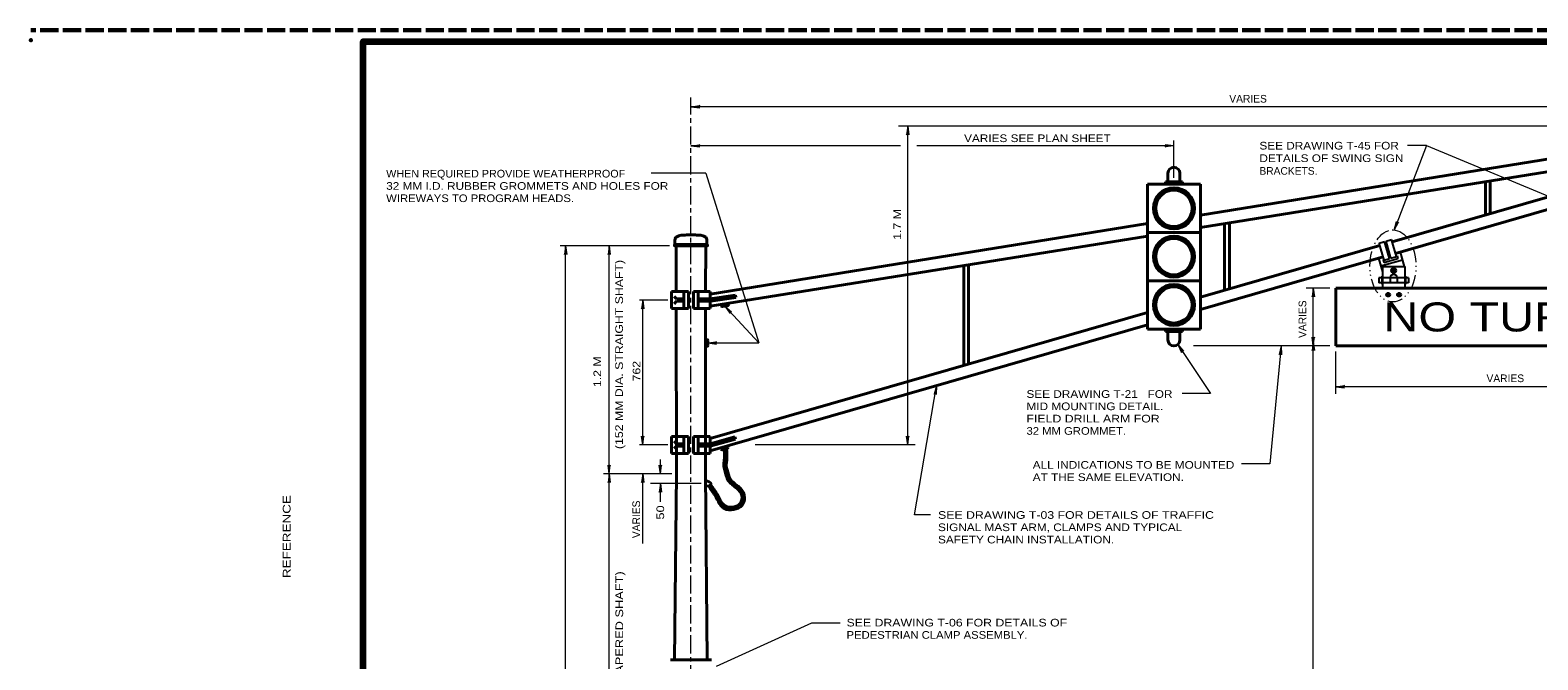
# Model space of a CAD drawing. Extents: x 312583 to 312853, y 144419 to 144586.
# Drawn here: x 312583.5 to 312733, y 144523.7 to 144586.2 of the extents above; entities that cross this region are included whole.
import ezdxf
from ezdxf.enums import TextEntityAlignment as Align

# ---------------------------------------------------------------- set-up
doc = ezdxf.new("R2010")
doc.units = 0
doc.header["$LTSCALE"] = 0.3
doc.header["$PDMODE"] = 32
doc.header["$PDSIZE"] = 0.15
for name, pattern in [('DASH_DOUBLE_DOT', [9.2, 5, -1.2, 0.3, -1.2, 0.3, -1.2]), ('LONG_DASH_SHORT_DASH', [9.9, 6, -1.2, 1.5, -1.2]), ('LONG_DASHED', [7.5, 6, -1.5])]:
    doc.linetypes.add(name, pattern=pattern)
for name, color, linetype, lineweight in [('1', 7, 'Continuous', 40), ('2', 7, 'Continuous', 13), ('63', 7, 'LONG_DASHED', 60)]:
    doc.layers.add(name, color=color, linetype=linetype, lineweight=lineweight)

msp = doc.modelspace()

# ---------------------------------------------------------------- hatches: boundary and pattern name
at = {"layer": '1'}
for points in [[(312718.9644, 144562.3791, 1), (312718.4824, 144562.3791, 1)], [(312718.8931, 144562.3791, 1), (312718.5537, 144562.3791, 1)], [(312718.3737, 144559.9738, 1), (312717.9914, 144559.9738, 1)], [(312719.4525, 144559.9738, 1), (312719.0702, 144559.9738, 1)]]:
    msp.add_hatch(color=256, dxfattribs=at).paths.add_polyline_path(points)

# ---------------------------------------------------------------- linework, layer by layer
for p, q in [((312699.5568, 144567.8759), (312754.2354, 144576.6849)), ((312699.5568, 144566.6493), (312754.4884, 144575.4813)), ((312696.0838, 144571.1803), (312697.7628, 144571.1803)), ((312696.0838, 144570.9426), (312696.0838, 144571.1803)), ((312696.3214, 144571.1803), (312696.3214, 144572.0236)), ((312697.5251, 144571.1803), (312697.5251, 144572.0236)), ((312697.7628, 144570.9426), (312697.7628, 144571.1803)), ((312718.5807, 144565.2268), (312740.3144, 144571.4967)), ((312727.8314, 144571.1956), (312727.8314, 144567.8989)), ((312728.3068, 144571.2723), (312728.3068, 144568.0369)), ((312694.2898, 144570.9426), (312699.5568, 144570.9426)), ((312694.2898, 144556.5676), (312694.2898, 144570.9426)), ((312699.5568, 144570.9426), (312699.5568, 144556.5676)), ((312718.9106, 144564.0723), (312740.6426, 144570.3417)), ((312650.9271, 144560.0406), (312694.2898, 144567.0249)), ((312701.9564, 144567.0326), (312701.9564, 144560.4316)), ((312702.4318, 144567.1093), (312702.4318, 144560.5696)), ((312647.4234, 144564.9549), (312647.4234, 144565.3153)), ((312650.5974, 144564.9549), (312650.5974, 144565.3153)), ((312650.9271, 144558.8293), (312694.2898, 144565.7983)), ((312694.2898, 144566.1509), (312699.5568, 144566.1509)), ((312650.5974, 144564.9549), (312647.3621, 144564.9549)), ((312647.5384, 144564.8323), (312649.0104, 144564.8323)), ((312647.5384, 144564.8323), (312647.5461, 144560.2783)), ((312650.4748, 144564.8323), (312649.0104, 144564.8323)), ((312650.4748, 144564.8323), (312650.4671, 144560.2783)), ((312650.5974, 144564.9549), (312650.6511, 144564.9549)), ((312699.5568, 144559.7416), (312717.3507, 144564.8725)), ((312699.5568, 144558.4919), (312717.6847, 144563.7192)), ((312717.8863, 144565.027), (312718.0344, 144565.0697)), ((312718.222, 144563.8741), (312718.3642, 144563.9151)), ((312676.0814, 144562.8696), (312676.0814, 144552.9719)), ((312676.5568, 144562.9463), (312676.5568, 144553.1099)), ((312694.2898, 144561.3593), (312699.5568, 144561.3593)), ((312747.5424, 144560.6386), (312712.9734, 144560.6386)), ((312712.9734, 144560.6386), (312712.9734, 144554.8886)), ((312647.0938, 144558.6069), (312647.0938, 144560.2783)), ((312648.7651, 144560.2783), (312647.0938, 144560.2783)), ((312647.3314, 144559.8029), (312647.5691, 144559.5653)), ((312647.3314, 144559.0823), (312647.5691, 144559.3199)), ((312648.2898, 144559.5653), (312647.5691, 144559.5653)), ((312648.2898, 144559.3199), (312647.5691, 144559.3199)), ((312648.2898, 144558.6069), (312648.2898, 144560.2783)), ((312648.7651, 144558.6069), (312648.7651, 144560.2783)), ((312649.2481, 144560.2783), (312650.9271, 144560.2783)), ((312649.2481, 144558.6069), (312649.2481, 144560.2783)), ((312649.7234, 144558.6069), (312649.7234, 144560.2783)), ((312650.9271, 144559.5653), (312649.7234, 144559.5653)), ((312650.9271, 144559.3199), (312649.7234, 144559.3199)), ((312650.9271, 144558.6069), (312650.9271, 144560.2783)), ((312650.9271, 144559.5653), (312653.4188, 144559.9409)), ((312650.9424, 144559.3199), (312653.4571, 144559.7109)), ((312653.4188, 144559.9409), (312653.4571, 144559.7109)), ((312648.7651, 144558.6069), (312647.0938, 144558.6069)), ((312647.5461, 144558.6069), (312647.5691, 144542.1926)), ((312649.2481, 144558.6069), (312650.9271, 144558.6069)), ((312650.4671, 144558.6069), (312650.4441, 144542.1926)), ((312650.9271, 144545.7116), (312694.2898, 144558.2236)), ((312652.0081, 144558.8829), (312651.9928, 144559.0056)), ((312652.1384, 144558.7986), (312652.6138, 144558.8676)), ((312652.7134, 144558.9903), (312652.6981, 144559.1129)), ((312650.9271, 144544.4696), (312694.2898, 144556.9739)), ((312694.2898, 144556.5676), (312699.5568, 144556.5676)), ((312696.0838, 144556.5676), (312696.0838, 144556.3299)), ((312696.0838, 144556.3299), (312697.7628, 144556.3299)), ((312696.3214, 144556.3299), (312696.3214, 144555.4866)), ((312697.5251, 144556.3299), (312697.5251, 144555.4866)), ((312697.7628, 144556.5676), (312697.7628, 144556.3299)), ((312650.5898, 144555.5479), (312650.4594, 144555.5479)), ((312650.5898, 144554.8349), (312650.4594, 144554.8349)), ((312650.6894, 144554.9499), (312650.6894, 144555.4329)), ((312747.5424, 144554.8886), (312712.9734, 144554.8886)), ((312647.0938, 144544.2319), (312647.0938, 144545.9033)), ((312648.7651, 144545.9033), (312647.0938, 144545.9033)), ((312648.2898, 144544.2319), (312648.2898, 144545.9033)), ((312648.7651, 144544.2319), (312648.7651, 144545.9033)), ((312649.2481, 144545.9033), (312650.9271, 144545.9033)), ((312649.2481, 144544.2319), (312649.2481, 144545.9033)), ((312649.7234, 144544.2319), (312649.7234, 144545.9033)), ((312650.9271, 144544.2319), (312650.9271, 144545.9033)), ((312650.9271, 144545.1903), (312653.3574, 144545.8573)), ((312653.3574, 144545.8573), (312653.4188, 144545.6273)), ((312648.7651, 144544.2319), (312647.0938, 144544.2319)), ((312647.3314, 144545.4279), (312647.5691, 144545.1903)), ((312647.3314, 144544.7073), (312647.5691, 144544.9449)), ((312648.2898, 144545.1903), (312647.5691, 144545.1903)), ((312648.2898, 144544.9449), (312647.5691, 144544.9449)), ((312649.2481, 144544.2319), (312650.9271, 144544.2319)), ((312650.9271, 144545.1903), (312649.7234, 144545.1903)), ((312650.9271, 144544.9449), (312649.7234, 144544.9449)), ((312650.9271, 144544.9373), (312653.4188, 144545.6273)), ((312652.0081, 144544.6613), (312651.9851, 144544.7609)), ((312652.1538, 144544.5923), (312652.6138, 144544.7149)), ((312652.6981, 144544.8453), (312652.6751, 144544.9526)), ((312647.5691, 144542.1926), (312647.3851, 144523.7466)), ((312650.4441, 144542.1926), (312650.6281, 144523.7466)), ((312651.0574, 144541.1806), (312650.6664, 144540.9429)), ((312651.0421, 144523.7466), (312646.9711, 144523.7466))]:
    msp.add_line(p, q, dxfattribs=at)
at = {"layer": '1', "lineweight": 25}
for p, q in [((312717.2873, 144565.0914), (312717.8244, 144565.2396)), ((312718.3152, 144563.5542), (312717.8244, 144565.2396)), ((312717.9726, 144565.2859), (312718.5189, 144565.4433)), ((312718.4541, 144563.6005), (312717.9726, 144565.2859)), ((312719.0004, 144563.7579), (312718.5189, 144565.4433)), ((312717.7781, 144563.3968), (312717.2873, 144565.0914)), ((312718.2874, 144563.6283), (312718.4448, 144563.6746)), ((312718.4541, 144563.6005), (312719.0004, 144563.7579)), ((312718.9819, 144563.8227), (312719.0653, 144563.8505)), ((312719.0653, 144563.8505), (312719.1486, 144563.5634)), ((312719.3616, 144564.2024), (312719.7681, 144562.7798)), ((312717.2317, 144563.5912), (312717.6214, 144562.2382)), ((312717.4547, 144562.8243), (312719.5846, 144563.4262)), ((312717.6214, 144562.7798), (312719.8254, 144562.7798)), ((312717.6214, 144562.7798), (312717.6214, 144560.6386)), ((312717.667, 144563.4523), (312717.7503, 144563.4708)), ((312717.667, 144563.4523), (312717.7503, 144563.156)), ((312717.7503, 144563.156), (312719.1486, 144563.5634)), ((312717.7781, 144563.3968), (312718.3152, 144563.5542)), ((312719.8254, 144562.7798), (312719.8254, 144560.6386)), ((312717.251, 144561.6484), (312717.251, 144561.1576)), ((312717.5473, 144561.6484), (312717.251, 144561.6484)), ((312717.5473, 144561.1576), (312717.251, 144561.1576)), ((312717.5473, 144561.8058), (312717.5473, 144561.0094)), ((312717.6214, 144561.8058), (312717.5473, 144561.8058)), ((312717.6214, 144561.0094), (312717.5473, 144561.0094)), ((312719.8254, 144561.6484), (312717.6214, 144561.6484)), ((312719.8254, 144561.1576), (312717.6214, 144561.1576)), ((312718.3715, 144561.6484), (312718.3715, 144561.1576)), ((312719.0753, 144561.6484), (312719.0753, 144561.1576)), ((312719.8994, 144561.8058), (312719.8254, 144561.8058)), ((312719.8994, 144561.0094), (312719.8254, 144561.0094)), ((312719.8994, 144561.8058), (312719.8994, 144561.0094)), ((312720.1958, 144561.6484), (312719.8994, 144561.6484)), ((312720.1958, 144561.1576), (312719.8994, 144561.1576)), ((312720.1958, 144561.6484), (312720.1958, 144561.1576))]:
    msp.add_line(p, q, dxfattribs=at)
at = {"layer": '1', "lineweight": 158}
msp.add_lwpolyline([(312616.5, 144423.1446), (312616.5, 144585.0846), (312849, 144585.0846)], dxfattribs=at)
at = {"layer": '1'}
for points in [[(312647.5384, 144564.8323), (312647.3621, 144564.8323), (312647.3621, 144564.9549)], [(312650.4748, 144564.8323), (312650.6511, 144564.8323), (312650.6511, 144564.9549)]]:
    msp.add_lwpolyline(points, dxfattribs=at)
for centre, radius in [((312696.9237, 144568.5458), 2.0365), ((312696.9237, 144568.5458), 1.7969), ((312696.9237, 144563.7541), 2.0365), ((312696.9237, 144563.7541), 1.7969), ((312696.9237, 144558.9625), 2.0365), ((312696.9237, 144558.9625), 1.7969)]:
    msp.add_circle(centre, radius, dxfattribs=at)
at = {"layer": '1', "lineweight": 25}
for centre, radius in [((312718.7234, 144562.3791), 0.241), ((312718.7234, 144562.3791), 0.1697), ((312718.1825, 144559.9738), 0.1911), ((312719.2613, 144559.9738), 0.1911)]:
    msp.add_circle(centre, radius, dxfattribs=at)
at = {"layer": '1'}
for centre, radius, start, end in [((312696.9237, 144572.0198), 0.599, 0, 180), ((312652.1231, 144558.9137), 0.1193, 195.83064, 278.98563), ((312652.5977, 144558.9866), 0.1193, 278.4852, 1.56735), ((312650.5731, 144554.9506), 0.1193, 277.08064, 0.23563), ((312650.5733, 144555.4308), 0.1193, 359.7352, 82.81735), ((312696.9237, 144555.4885), 0.599, 180, 0), ((312652.1198, 144544.7035), 0.1193, 202.50814, 285.66313), ((312652.5827, 144544.831), 0.1193, 285.1627, 8.24485), ((312650.5009, 144540.8365), 0.6575, 31.85561, 93.74313), ((312650.5009, 144540.8365), 0.1989, 31.87604, 102.98389)]:
    msp.add_arc(centre, radius, start, end, dxfattribs=at)
at = {"layer": '1', "lineweight": 25}
msp.add_arc((312718.7219, 144561.6237), 0.3533, 5.25702, 174.74298, dxfattribs=at)
at = {"layer": '1', "linetype": 'DASH_DOUBLE_DOT', "lineweight": 13}
msp.add_ellipse((312718.6496, 144562.8307), major_axis=(0, 3.5708), ratio=0.640077, dxfattribs=at)
at = {"layer": '1'}
for points in [[(312649.0104, 144565.9133), (312648.6654, 144565.9056), (312648.2284, 144565.8826), (312648.0214, 144565.8673), (312647.8144, 144565.8213), (312647.6688, 144565.7599), (312647.5384, 144565.6756), (312647.4464, 144565.5376), (312647.4311, 144565.4763), (312647.4234, 144565.3153)], [(312649.0104, 144565.9133), (312649.3478, 144565.9056), (312649.7848, 144565.8826), (312649.9918, 144565.8673), (312650.1988, 144565.8213), (312650.3444, 144565.7599), (312650.4748, 144565.6756), (312650.5668, 144565.5376), (312650.5821, 144565.4763), (312650.5974, 144565.3153)], [(312652.5371, 144544.6843), (312652.5524, 144543.5266), (312652.5064, 144543.0589), (312652.5984, 144542.5989), (312652.9204, 144541.6866), (312653.6871, 144540.9659), (312654.1011, 144540.5443), (312654.3158, 144539.6243), (312654.0781, 144539.0953), (312653.2501, 144538.6583), (312652.3378, 144538.7503), (312651.8471, 144539.2409), (312651.3948, 144540.0766), (312651.0651, 144540.5366), (312650.7584, 144540.9966)], [(312652.2994, 144544.6383), (312652.3148, 144543.5419), (312652.2688, 144543.0513), (312652.3684, 144542.5376), (312652.7134, 144541.5486), (312653.5184, 144540.7973), (312653.8864, 144540.4216), (312654.0628, 144539.6473), (312653.8941, 144539.2716), (312653.2041, 144538.9036), (312652.4528, 144538.9803), (312652.0388, 144539.3866), (312651.5941, 144540.1993), (312651.2644, 144540.6746), (312650.9578, 144541.1269)]]:
    msp.add_spline(points, degree=3, dxfattribs=at)
msp.add_point((312583.526, 144585.2246), dxfattribs=at)
at = {"layer": '2', "linetype": 'LONG_DASH_SHORT_DASH'}
msp.add_line((312649.0104, 144438.2556), (312649.0104, 144579.5523), dxfattribs=at)
at = {"layer": '2'}
for p, q in [((312649.0104, 144578.6323), (312649.8768, 144578.7396)), ((312763.5274, 144578.6323), (312649.0104, 144578.6323)), ((312649.0104, 144578.6323), (312649.8768, 144578.5249)), ((312649.8768, 144578.7396), (312649.6008, 144578.6323)), ((312649.8768, 144578.5249), (312649.6008, 144578.6323)), ((312751.6901, 144576.6926), (312669.5878, 144576.6926)), ((312670.5154, 144576.6926), (312670.4081, 144575.8263)), ((312670.4081, 144575.8263), (312670.5154, 144576.1023)), ((312670.5154, 144545.0676), (312670.5154, 144576.6926)), ((312670.5154, 144576.6926), (312670.6228, 144575.8263)), ((312670.6228, 144575.8263), (312670.5154, 144576.1023)), ((312649.0104, 144574.7529), (312649.8768, 144574.8603)), ((312669.8024, 144574.7529), (312649.0104, 144574.7529)), ((312649.0104, 144574.7529), (312649.8768, 144574.6456)), ((312649.8768, 144574.8603), (312649.6008, 144574.7529)), ((312649.8768, 144574.6456), (312649.6008, 144574.7529)), ((312696.9271, 144574.7529), (312671.4201, 144574.7529)), ((312696.0608, 144574.8603), (312696.3368, 144574.7529)), ((312696.9271, 144574.7529), (312696.0608, 144574.8603)), ((312696.0608, 144574.6456), (312696.3368, 144574.7529)), ((312696.9271, 144574.7529), (312696.0608, 144574.6456)), ((312696.9271, 144571.5559), (312696.9271, 144575.2896)), ((312721.9663, 144574.7864), (312718.7871, 144566.395)), ((312721.9663, 144574.7864), (312720.11, 144574.7864)), ((312721.9663, 144574.7864), (312738.6993, 144567.8305)), ((312650.4978, 144572.0236), (312645.0544, 144572.0236)), ((312650.4978, 144572.0236), (312655.7341, 144555.1876)), ((312718.7871, 144566.395), (312718.9906, 144567.2466)), ((312718.7871, 144566.395), (312719.1934, 144567.1692)), ((312718.9906, 144567.2466), (312718.996, 144566.9483)), ((312719.1934, 144567.1692), (312718.996, 144566.9483)), ((312646.8714, 144564.8323), (312636.0461, 144564.8323)), ((312636.5751, 144564.8323), (312636.4678, 144563.9659)), ((312636.4678, 144563.9659), (312636.5751, 144564.2419)), ((312636.5751, 144471.2759), (312636.5751, 144564.8323)), ((312636.5751, 144564.8323), (312636.6824, 144563.9659)), ((312636.6824, 144563.9659), (312636.5751, 144564.2419)), ((312640.8914, 144564.8323), (312640.7841, 144563.9659)), ((312640.7841, 144563.9659), (312640.8914, 144564.2419)), ((312640.8914, 144542.1926), (312640.8914, 144564.8323)), ((312640.8914, 144564.8323), (312640.9988, 144563.9659)), ((312640.9988, 144563.9659), (312640.8914, 144564.2419)), ((312712.4061, 144560.6386), (312710.0371, 144560.6386)), ((312710.7501, 144560.6386), (312710.6428, 144559.7723)), ((312710.7501, 144554.8886), (312710.7501, 144560.6386)), ((312710.7501, 144560.6386), (312710.8574, 144559.7723)), ((312646.7181, 144559.4426), (312643.9044, 144559.4426)), ((312644.2188, 144559.4426), (312644.1114, 144558.5763)), ((312644.2188, 144545.0676), (312644.2188, 144559.4426)), ((312644.2188, 144559.4426), (312644.3261, 144558.5763)), ((312710.6428, 144559.7723), (312710.7501, 144560.0483)), ((312710.8574, 144559.7723), (312710.7501, 144560.0483)), ((312644.1114, 144558.5763), (312644.2188, 144558.8523)), ((312644.3261, 144558.5763), (312644.2188, 144558.8523)), ((312652.3761, 144558.8293), (312655.7341, 144555.1876)), ((312652.3761, 144558.8293), (312652.8898, 144558.1239)), ((312652.3761, 144558.8293), (312653.0431, 144558.2696)), ((312652.8898, 144558.1239), (312652.7824, 144558.3999)), ((312653.0431, 144558.2696), (312652.7824, 144558.3999)), ((312650.6894, 144555.1876), (312651.5558, 144555.2949)), ((312650.6894, 144555.1876), (312655.7341, 144555.1876)), ((312650.6894, 144555.1876), (312651.5558, 144555.0803)), ((312651.5558, 144555.2949), (312651.2798, 144555.1876)), ((312651.5558, 144555.0803), (312651.2798, 144555.1876)), ((312697.2951, 144555.0189), (312700.5611, 144550.1736)), ((312697.2951, 144555.0189), (312697.6861, 144554.2369)), ((312697.2951, 144555.0189), (312697.8624, 144554.3596)), ((312712.4061, 144554.8886), (312698.8744, 144554.8886)), ((312707.5684, 144554.8886), (312706.4491, 144543.2046)), ((312707.5684, 144554.8886), (312707.3768, 144554.0376)), ((312707.5684, 144554.8886), (312707.5914, 144554.0146)), ((312710.6428, 144555.7549), (312710.7501, 144555.4789)), ((312710.7501, 144554.8886), (312710.6428, 144555.7549)), ((312710.7501, 144555.2949), (312710.6428, 144554.4286)), ((312710.6428, 144554.4286), (312710.7501, 144554.7046)), ((312710.8574, 144555.7549), (312710.7501, 144555.4789)), ((312710.7501, 144554.8886), (312710.8574, 144555.7549)), ((312710.7501, 144456.4179), (312710.7501, 144555.2949)), ((312710.7501, 144555.2949), (312710.8574, 144554.4286)), ((312710.8574, 144554.4286), (312710.7501, 144554.7046)), ((312697.6861, 144554.2369), (312697.6248, 144554.5283)), ((312697.8624, 144554.3596), (312697.6248, 144554.5283)), ((312707.3768, 144554.0376), (312707.5071, 144554.3059)), ((312707.5914, 144554.0146), (312707.5071, 144554.3059)), ((312712.9734, 144550.1353), (312712.9734, 144554.3366)), ((312671.1704, 144538.1216), (312673.3828, 144550.9479)), ((312673.3828, 144550.9479), (312673.1342, 144550.1099)), ((312673.1342, 144550.1099), (312673.281, 144550.3616)), ((312673.3452, 144550.0748), (312673.281, 144550.3616)), ((312673.3828, 144550.9479), (312673.3452, 144550.0748)), ((312700.5611, 144550.1736), (312697.7321, 144550.1736)), ((312712.9734, 144550.8483), (312713.8398, 144550.9556)), ((312747.5424, 144550.8483), (312712.9734, 144550.8483)), ((312712.9734, 144550.8483), (312713.8398, 144550.7409)), ((312713.8398, 144550.9556), (312713.5638, 144550.8483)), ((312713.8398, 144550.7409), (312713.5638, 144550.8483)), ((312644.1114, 144545.9339), (312644.2188, 144545.6579)), ((312644.2188, 144545.0676), (312644.1114, 144545.9339)), ((312644.3261, 144545.9339), (312644.2188, 144545.6579)), ((312644.2188, 144545.0676), (312644.3261, 144545.9339)), ((312670.4081, 144545.9339), (312670.5154, 144545.6579)), ((312670.5154, 144545.0676), (312670.4081, 144545.9339)), ((312670.6228, 144545.9339), (312670.5154, 144545.6579)), ((312670.5154, 144545.0676), (312670.6228, 144545.9339)), ((312646.7181, 144545.0676), (312643.9044, 144545.0676)), ((312671.2438, 144545.0676), (312655.3891, 144545.0676)), ((312640.7841, 144543.0589), (312640.8914, 144542.7829)), ((312640.8914, 144542.1926), (312640.7841, 144543.0589)), ((312640.9988, 144543.0589), (312640.8914, 144542.7829)), ((312640.8914, 144542.1926), (312640.9988, 144543.0589)), ((312645.8671, 144543.0589), (312645.9744, 144542.7829)), ((312645.9744, 144542.1926), (312645.8671, 144543.0589)), ((312645.9744, 144542.1926), (312645.9744, 144543.6263)), ((312646.0818, 144543.0589), (312645.9744, 144542.7829)), ((312645.9744, 144542.1926), (312646.0818, 144543.0589)), ((312706.4491, 144543.2046), (312703.6278, 144543.2046)), ((312647.1244, 144542.1926), (312640.3394, 144542.1926)), ((312640.8914, 144542.1926), (312640.7841, 144541.3263)), ((312640.7841, 144541.3263), (312640.8914, 144541.6023)), ((312640.8914, 144494.2759), (312640.8914, 144542.1926)), ((312640.8914, 144542.1926), (312640.9988, 144541.3263)), ((312640.9988, 144541.3263), (312640.8914, 144541.6023)), ((312644.2188, 144542.1926), (312644.1114, 144541.3263)), ((312644.1114, 144541.3263), (312644.2188, 144541.6023)), ((312644.2188, 144535.2773), (312644.2188, 144542.1926)), ((312644.2188, 144542.1926), (312644.3261, 144541.3263)), ((312644.3261, 144541.3263), (312644.2188, 144541.6023)), ((312650.0224, 144541.2343), (312645.0084, 144541.2343)), ((312645.9744, 144541.2343), (312645.8671, 144540.3679)), ((312645.9744, 144539.4249), (312645.9744, 144541.2343)), ((312645.9744, 144541.2343), (312646.0818, 144540.3679)), ((312645.8671, 144540.3679), (312645.9744, 144540.6439)), ((312646.0818, 144540.3679), (312645.9744, 144540.6439)), ((312672.7694, 144538.1216), (312671.1704, 144538.1216)), ((312660.9781, 144527.3883), (312651.5098, 144523.0796)), ((312663.8071, 144527.3883), (312660.9781, 144527.3883))]:
    msp.add_line(p, q, dxfattribs=at)
at = {"layer": '63'}
msp.add_line((312851.75, 144586.2246), (312583.526, 144586.2246), dxfattribs=at)

# ---------------------------------------------------------------- texts
at = {"layer": '1', "width": 1.25}
msp.add_text('NO TURNS', height=2.875, dxfattribs=at).set_placement((312730.2579, 144556.3299), align=Align.CENTER)
at = {"layer": '1', "width": 1.3}
msp.add_text('REFERENCE                                                              ', height=0.7682, rotation=90, dxfattribs=at).set_placement((312609.2854, 144531.8549))
at = {"layer": '2'}
for s, p in [('VARIES', (312702.4164, 144579.0376)), ('BRACKETS.', (312705.403, 144571.8797)), ('VARIES', (312727.933, 144551.2996))]:
    msp.add_text(s, height=0.76, dxfattribs=at).set_placement(p)
for s, width, p in [('VARIES SEE PLAN SHEET', 1.15, (312676.1076, 144575.118)), ('SEE DRAWING T-45 FOR', 1.15, (312705.4038, 144574.3821)), ('DETAILS OF SWING SIGN', 1.15, (312705.4038, 144573.137)), ('WHEN REQUIRED PROVIDE WEATHERPROOF', 1.05, (312618.7732, 144571.6047)), ('32 MM I.D. RUBBER GROMMETS AND HOLES FOR', 1.15, (312618.7732, 144570.3847)), ('WIREWAYS TO PROGRAM HEADS.', 1.1, (312618.7732, 144569.1647)), ('SEE DRAWING T-21   FOR', 1.15, (312682.2953, 144549.7395)), ('MID MOUNTING DETAIL.', 1.15, (312682.2953, 144548.5195)), ('FIELD DRILL ARM FOR', 1.2, (312682.2953, 144547.2995)), ('32 MM GROMMET.', 1.1, (312682.2953, 144546.0795)), ('ALL INDICATIONS TO BE MOUNTED', 1.15, (312682.9138, 144542.7091)), ('AT THE SAME ELEVATION.', 1.15, (312682.9138, 144541.4891)), ('SEE DRAWING T-03 FOR DETAILS OF TRAFFIC', 1.2, (312673.5208, 144537.7373)), ('SIGNAL MAST ARM, CLAMPS AND TYPICAL', 1.15, (312673.5208, 144536.5173)), ('SAFETY CHAIN INSTALLATION.', 1.15, (312673.5208, 144535.2973)), ('SEE DRAWING T-06 FOR DETAILS OF', 1.2, (312664.4434, 144527.0576)), ('PEDESTRIAN CLAMP ASSEMBLY.', 1.1, (312664.4434, 144525.8376))]:
    msp.add_text(s, height=0.76, dxfattribs=dict(at, width=width)).set_placement(p)
for s, width, p in [('1.7 M', 1.2, (312669.8596, 144565.4207)), ('(152 MM DIA. STRAIGHT SHAFT)', 1.2, (312642.2608, 144544.659)), ('1.2 M', 1.2, (312640.0978, 144550.8089)), ('762 ', 1.2, (312643.9883, 144551.3709)), ('50 ', 1.25, (312646.3457, 144537.6632)), ('(203 MM DIA. TO 152 MM DIA. TAPERED SHAFT)', 1.25, (312642.2801, 144503.5195))]:
    msp.add_text(s, height=0.76, rotation=90, dxfattribs=dict(at, width=width)).set_placement(p)
for p in [(312710.0518, 144555.6822), (312643.9591, 144535.8216)]:
    msp.add_text('VARIES', height=0.76, rotation=90, dxfattribs=at).set_placement(p)

doc.saveas('drawing.dxf')
